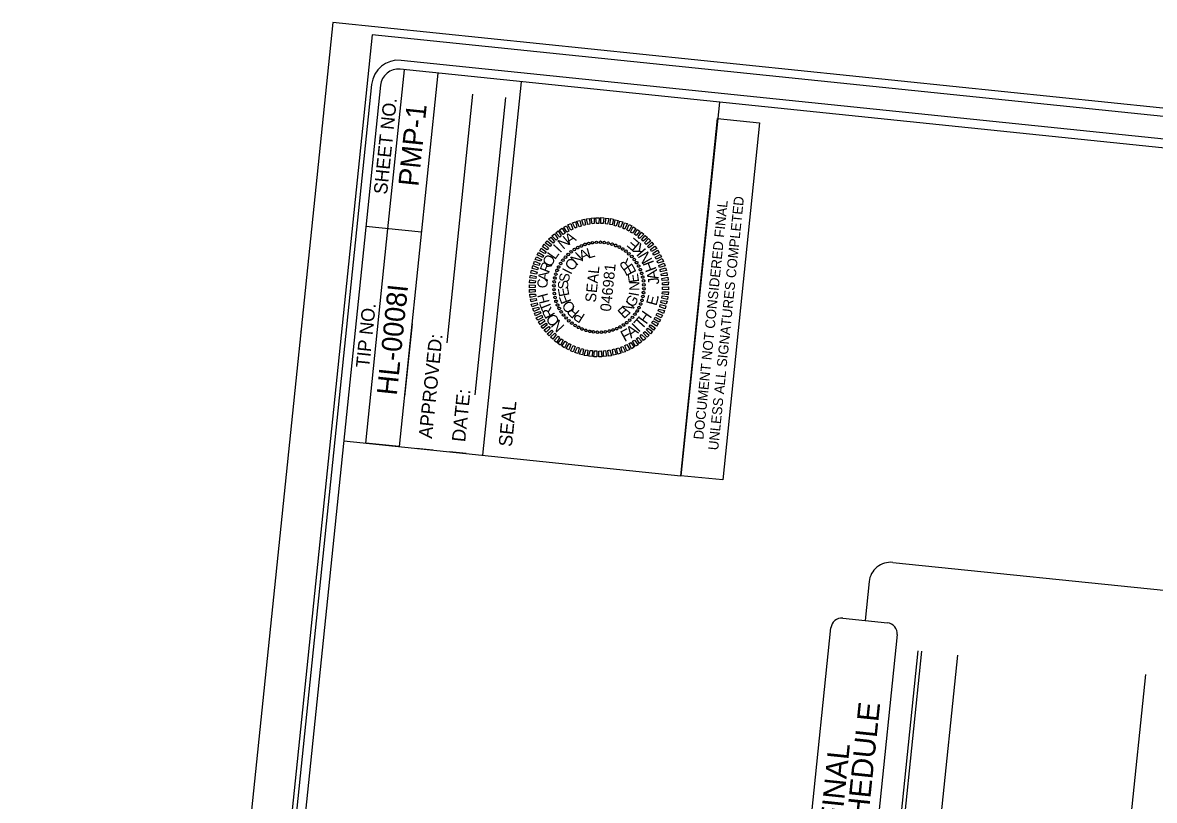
# Model space of a CAD drawing. Extents: x 2077770 to 2079037, y 247476 to 249877.
# Drawn here: x 2077770 to 2078401, y 249383 to 249816 of the extents above; entities that cross this region are included whole.
import ezdxf

# ---------------------------------------------------------------- set-up
doc = ezdxf.new("R2010")
doc.units = 0
for name, color, linetype in [('Default', 7, 'Continuous'), ('Sheet Data Field CELL', 7, 'Continuous'), ('Sheet Plot Border Inside CELL', 7, 'Continuous'), ('Sheet Plot Border Outside CELL', 7, 'Continuous'), ('Sheet Sticker Exception Certification CELL', 7, 'Continuous'), ('Sheet Title CELL', 7, 'Continuous')]:
    doc.layers.add(name, color=color, linetype=linetype)

msp = doc.modelspace()

# ---------------------------------------------------------------- linework, layer by layer
at = {"layer": 'Default'}
for p, q in [((2078081.68, 249691.84), (2078081.68, 249691.84)), ((2078083.72, 249692.63), (2078083.72, 249692.63)), ((2078085.79, 249693.22), (2078085.79, 249693.22)), ((2078087.94, 249693.61), (2078087.94, 249693.61)), ((2078090.17, 249693.78), (2078090.17, 249693.78)), ((2078092.34, 249693.85), (2078092.34, 249693.85)), ((2078094.53, 249693.68), (2078094.53, 249693.68)), ((2078096.71, 249693.3), (2078096.71, 249693.3)), ((2078098.81, 249692.73), (2078098.81, 249692.73)), ((2078100.85, 249692.07), (2078100.85, 249692.07)), ((2078072.83, 249685.51), (2078072.83, 249685.51)), ((2078074.35, 249687.12), (2078074.35, 249687.12)), ((2078076, 249688.5), (2078076, 249688.5)), ((2078077.8, 249689.83), (2078077.8, 249689.83)), ((2078079.67, 249690.89), (2078079.67, 249690.89)), ((2078102.87, 249691.16), (2078102.87, 249691.16)), ((2078104.77, 249690.06), (2078104.77, 249690.06)), ((2078106.6, 249688.86), (2078106.6, 249688.86)), ((2078108.27, 249687.44), (2078108.27, 249687.44)), ((2078109.87, 249685.91), (2078109.87, 249685.91)), ((2078069.11, 249680.12), (2078069.11, 249680.12)), ((2078070.21, 249682.01), (2078070.21, 249682.01)), ((2078071.4, 249683.85), (2078071.4, 249683.85)), ((2078111.26, 249684.26), (2078111.26, 249684.26)), ((2078112.58, 249682.47), (2078112.58, 249682.47)), ((2078113.64, 249680.6), (2078113.64, 249680.6)), ((2078066.96, 249673.96), (2078066.96, 249673.96)), ((2078067.53, 249676.06), (2078067.53, 249676.06)), ((2078068.2, 249678.1), (2078068.2, 249678.1)), ((2078114.59, 249678.59), (2078114.59, 249678.59)), ((2078115.39, 249676.55), (2078115.39, 249676.55)), ((2078115.98, 249674.48), (2078115.98, 249674.48)), ((2078066.41, 249669.59), (2078066.41, 249669.59)), ((2078066.49, 249667.42), (2078066.49, 249667.42)), ((2078066.59, 249671.78), (2078066.59, 249671.78)), ((2078091.51, 249668.76), (2078091.51, 249668.76)), ((2078116.36, 249672.33), (2078116.36, 249672.33)), ((2078116.53, 249670.1), (2078116.53, 249670.1)), ((2078116.61, 249667.93), (2078116.61, 249667.93)), ((2078066.66, 249665.19), (2078066.66, 249665.19)), ((2078067.04, 249663.04), (2078067.04, 249663.04)), ((2078067.63, 249660.97), (2078067.63, 249660.97)), ((2078115.49, 249661.46), (2078115.49, 249661.46)), ((2078116.06, 249663.56), (2078116.06, 249663.56)), ((2078116.43, 249665.73), (2078116.43, 249665.73)), ((2078068.43, 249658.93), (2078068.43, 249658.93)), ((2078069.38, 249656.92), (2078069.38, 249656.92)), ((2078070.44, 249655.05), (2078070.44, 249655.05)), ((2078112.81, 249655.5), (2078112.81, 249655.5)), ((2078113.91, 249657.4), (2078113.91, 249657.4)), ((2078114.82, 249659.41), (2078114.82, 249659.41)), ((2078071.76, 249653.25), (2078071.76, 249653.25)), ((2078073.15, 249651.6), (2078073.15, 249651.6)), ((2078074.75, 249650.08), (2078074.75, 249650.08)), ((2078076.42, 249648.65), (2078076.42, 249648.65)), ((2078078.25, 249647.46), (2078078.25, 249647.46)), ((2078105.22, 249647.69), (2078105.22, 249647.69)), ((2078107.01, 249649.01), (2078107.01, 249649.01)), ((2078108.67, 249650.4), (2078108.67, 249650.4)), ((2078110.19, 249652), (2078110.19, 249652)), ((2078111.62, 249653.66), (2078111.62, 249653.66)), ((2078080.15, 249646.36), (2078080.15, 249646.36)), ((2078082.17, 249645.44), (2078082.17, 249645.44)), ((2078084.21, 249644.78), (2078084.21, 249644.78)), ((2078086.31, 249644.21), (2078086.31, 249644.21)), ((2078088.48, 249643.84), (2078088.48, 249643.84)), ((2078090.68, 249643.66), (2078090.68, 249643.66)), ((2078092.85, 249643.74), (2078092.85, 249643.74)), ((2078095.08, 249643.91), (2078095.08, 249643.91)), ((2078097.23, 249644.29), (2078097.23, 249644.29)), ((2078099.3, 249644.88), (2078099.3, 249644.88)), ((2078101.34, 249645.68), (2078101.34, 249645.68)), ((2078103.35, 249646.62), (2078103.35, 249646.62)), ((2078237.64, 249157.39), (2078269.5, 249466.05)), ((2078239.63, 249157.18), (2078271.49, 249465.85)), ((2078259.7, 249155.11), (2078291.55, 249463.77)), ((2078364.43, 249144.31), (2078396.28, 249452.98))]:
    msp.add_line(p, q, dxfattribs=at)
for points in [[(2078075.9, 249700.63), (2078074.28, 249703.46), (2078075.87, 249704.25), (2078076.97, 249701.22)], [(2078078.22, 249701.7), (2078076.77, 249704.66), (2078078.38, 249705.15), (2078079.23, 249702.2)], [(2078080.46, 249702.47), (2078079.27, 249705.56), (2078080.93, 249706.04), (2078081.61, 249702.85)], [(2078082.89, 249703.12), (2078081.91, 249706.29), (2078083.51, 249706.68), (2078083.99, 249703.51)], [(2078085.36, 249703.67), (2078084.55, 249706.97), (2078086.22, 249707.1), (2078086.44, 249703.91)], [(2078087.81, 249704.02), (2078087.19, 249707.25), (2078088.91, 249707.38), (2078088.89, 249704.21)], [(2078090.24, 249704.22), (2078089.88, 249707.53), (2078091.59, 249707.5), (2078091.46, 249704.3)], [(2078092.66, 249704.28), (2078092.6, 249707.55), (2078094.3, 249707.48), (2078093.87, 249704.25)], [(2078095.15, 249704.07), (2078095.34, 249707.32), (2078097.03, 249707.14), (2078096.35, 249703.95)], [(2078097.64, 249703.76), (2078098.07, 249706.99), (2078099.7, 249706.72), (2078098.82, 249703.54)], [(2078100, 249703.27), (2078100.62, 249706.42), (2078102.29, 249706.05), (2078101.17, 249702.9)], [(2078102.49, 249702.61), (2078103.21, 249705.65), (2078104.86, 249705.13), (2078103.5, 249702.1)], [(2078104.81, 249701.72), (2078105.78, 249704.73), (2078107.38, 249704.22), (2078105.82, 249701.21)], [(2078067.74, 249695.09), (2078065.36, 249697.39), (2078066.68, 249698.46), (2078068.58, 249695.96)], [(2078069.66, 249696.7), (2078067.55, 249699.08), (2078068.86, 249700.15), (2078070.54, 249697.36)], [(2078071.63, 249698.25), (2078069.63, 249700.77), (2078071.08, 249701.68), (2078072.7, 249698.85)], [(2078073.73, 249699.55), (2078071.89, 249702.2), (2078073.43, 249702.99), (2078074.73, 249700.05)], [(2078107.12, 249700.72), (2078108.34, 249703.71), (2078109.81, 249702.91), (2078108.11, 249700.07)], [(2078109.21, 249699.5), (2078110.67, 249702.47), (2078112.14, 249701.56), (2078110.25, 249698.89)], [(2078111.39, 249698.27), (2078112.93, 249700.98), (2078114.4, 249700.07), (2078112.28, 249697.58)], [(2078113.41, 249696.86), (2078115.19, 249699.49), (2078116.48, 249698.35), (2078114.22, 249695.97)], [(2078062.75, 249689.67), (2078060.06, 249691.31), (2078061.06, 249692.71), (2078063.45, 249690.55)], [(2078064.3, 249691.47), (2078061.59, 249693.51), (2078062.77, 249694.7), (2078065.01, 249692.5)], [(2078066, 249693.36), (2078063.45, 249695.48), (2078064.68, 249696.66), (2078066.79, 249694.23)], [(2078115.25, 249695.16), (2078117.21, 249697.67), (2078118.56, 249696.58), (2078116.12, 249694.42)], [(2078116.98, 249693.47), (2078119.19, 249695.86), (2078120.37, 249694.63), (2078117.8, 249692.68)], [(2078118.69, 249691.54), (2078120.99, 249693.86), (2078122.01, 249692.5), (2078119.41, 249690.66)], [(2078120.26, 249689.72), (2078122.68, 249691.68), (2078123.75, 249690.36), (2078120.86, 249688.7)], [(2078059.07, 249683.21), (2078056.07, 249684.28), (2078056.72, 249685.77), (2078059.53, 249684.22)], [(2078060.2, 249685.36), (2078057.18, 249686.83), (2078057.92, 249688.16), (2078060.66, 249686.47)], [(2078061.37, 249687.5), (2078058.57, 249689.05), (2078059.42, 249690.52), (2078062.03, 249688.54)], [(2078121.6, 249687.57), (2078124.21, 249689.46), (2078125.11, 249688.01), (2078122.15, 249686.56)], [(2078122.9, 249685.52), (2078125.62, 249687.1), (2078126.43, 249685.71), (2078123.38, 249684.37)], [(2078057.37, 249678.41), (2078054.23, 249679.19), (2078054.65, 249680.81), (2078057.64, 249679.59)], [(2078058.18, 249680.89), (2078055, 249681.72), (2078055.57, 249683.37), (2078058.54, 249681.91)], [(2078123.91, 249683.21), (2078126.79, 249684.77), (2078127.43, 249683.15), (2078124.41, 249682.2)], [(2078124.89, 249680.95), (2078127.84, 249682.25), (2078128.37, 249680.64), (2078125.22, 249679.8)], [(2078125.71, 249678.65), (2078128.72, 249679.64), (2078129.17, 249678.09), (2078125.88, 249677.37)], [(2078056.02, 249671.21), (2078052.77, 249671.3), (2078052.98, 249672.93), (2078056.2, 249672.4)], [(2078056.32, 249673.6), (2078053.09, 249673.93), (2078053.31, 249675.57), (2078056.49, 249674.78)], [(2078056.73, 249676.07), (2078053.51, 249676.6), (2078053.98, 249678.21), (2078057.05, 249677.24)], [(2078126.25, 249676.13), (2078129.35, 249676.97), (2078129.64, 249675.38), (2078126.49, 249675.05)], [(2078126.65, 249673.68), (2078129.89, 249674.4), (2078130.06, 249672.67), (2078126.79, 249672.61)], [(2078056.02, 249668.7), (2078052.78, 249668.48), (2078052.75, 249670.19), (2078055.99, 249669.91)], [(2078056.07, 249666.28), (2078052.8, 249665.82), (2078052.82, 249667.47), (2078056.04, 249667.49)], [(2078126.95, 249671.23), (2078130.22, 249671.7), (2078130.2, 249670.04), (2078126.98, 249670.02)], [(2078127, 249668.81), (2078130.24, 249669.03), (2078130.27, 249667.32), (2078127.03, 249667.6)], [(2078056.37, 249663.84), (2078053.13, 249663.12), (2078052.95, 249664.85), (2078056.23, 249664.91)], [(2078056.77, 249661.39), (2078053.67, 249660.55), (2078053.38, 249662.14), (2078056.53, 249662.47)], [(2078057.31, 249658.87), (2078054.3, 249657.87), (2078053.85, 249659.42), (2078057.14, 249660.14)], [(2078126.29, 249661.45), (2078129.51, 249660.92), (2078129.04, 249659.3), (2078125.97, 249660.27)], [(2078126.7, 249663.92), (2078129.93, 249663.59), (2078129.71, 249661.95), (2078126.53, 249662.73)], [(2078126.99, 249666.3), (2078130.25, 249666.22), (2078130.03, 249664.58), (2078126.82, 249665.11)], [(2078058.13, 249656.57), (2078055.18, 249655.27), (2078054.65, 249656.88), (2078057.8, 249657.71)], [(2078059.1, 249654.31), (2078056.23, 249652.75), (2078055.59, 249654.37), (2078058.61, 249655.31)], [(2078123.95, 249654.3), (2078126.95, 249653.24), (2078126.3, 249651.75), (2078123.49, 249653.29)], [(2078124.84, 249656.62), (2078128.02, 249655.79), (2078127.45, 249654.14), (2078124.48, 249655.6)], [(2078125.65, 249659.1), (2078128.79, 249658.33), (2078128.37, 249656.71), (2078125.38, 249657.92)], [(2078060.12, 249651.99), (2078057.4, 249650.41), (2078056.58, 249651.8), (2078059.64, 249653.15)], [(2078061.42, 249649.95), (2078058.81, 249648.06), (2078057.91, 249649.51), (2078060.87, 249650.96)], [(2078062.76, 249647.8), (2078060.34, 249645.84), (2078059.27, 249647.15), (2078062.16, 249648.82)], [(2078120.26, 249647.84), (2078122.96, 249646.21), (2078121.96, 249644.8), (2078119.57, 249646.96)], [(2078121.64, 249650.01), (2078124.45, 249648.47), (2078123.6, 249647), (2078120.98, 249648.98)], [(2078122.82, 249652.16), (2078125.84, 249650.69), (2078125.1, 249649.36), (2078122.35, 249651.05)], [(2078064.33, 249645.98), (2078062.03, 249643.65), (2078061.01, 249645.01), (2078063.61, 249646.86)], [(2078066.04, 249644.04), (2078063.83, 249641.66), (2078062.65, 249642.88), (2078065.21, 249644.83)], [(2078067.77, 249642.35), (2078065.81, 249639.84), (2078064.46, 249640.94), (2078066.9, 249643.1)], [(2078069.61, 249640.66), (2078067.83, 249638.03), (2078066.54, 249639.16), (2078068.8, 249641.55)], [(2078115.28, 249642.43), (2078117.66, 249640.12), (2078116.34, 249639.05), (2078114.44, 249641.56)], [(2078117.02, 249644.16), (2078119.56, 249642.04), (2078118.34, 249640.86), (2078116.22, 249643.29)], [(2078118.72, 249646.04), (2078121.43, 249644.01), (2078120.25, 249642.82), (2078118.01, 249645.01)], [(2078071.62, 249639.24), (2078070.09, 249636.54), (2078068.62, 249637.44), (2078070.74, 249639.94)], [(2078073.81, 249638.01), (2078072.35, 249635.05), (2078070.88, 249635.95), (2078072.77, 249638.62)], [(2078075.9, 249636.79), (2078074.68, 249633.8), (2078073.21, 249634.61), (2078074.91, 249637.45)], [(2078078.21, 249635.8), (2078077.24, 249632.78), (2078075.64, 249633.3), (2078077.2, 249636.3)], [(2078080.53, 249634.91), (2078079.81, 249631.86), (2078078.15, 249632.39), (2078079.52, 249635.41)], [(2078102.56, 249635.05), (2078103.75, 249631.96), (2078102.09, 249631.47), (2078101.41, 249634.66)], [(2078104.8, 249635.82), (2078106.25, 249632.85), (2078104.64, 249632.37), (2078103.79, 249635.32)], [(2078107.12, 249636.89), (2078108.74, 249634.06), (2078107.15, 249633.26), (2078106.05, 249636.29)], [(2078109.29, 249637.97), (2078111.13, 249635.32), (2078109.59, 249634.52), (2078108.29, 249637.47)], [(2078111.39, 249639.26), (2078113.39, 249636.74), (2078111.94, 249635.84), (2078110.32, 249638.67)], [(2078113.36, 249640.82), (2078115.47, 249638.44), (2078114.16, 249637.37), (2078112.48, 249640.15)], [(2078083.02, 249634.25), (2078082.39, 249631.09), (2078080.72, 249631.47), (2078081.85, 249634.62)], [(2078085.38, 249633.75), (2078084.95, 249630.53), (2078083.32, 249630.8), (2078084.2, 249633.97)], [(2078087.86, 249633.45), (2078087.68, 249630.2), (2078085.99, 249630.37), (2078086.67, 249633.57)], [(2078090.36, 249633.24), (2078090.42, 249629.96), (2078088.72, 249630.04), (2078089.15, 249633.26)], [(2078092.77, 249633.29), (2078093.14, 249629.99), (2078091.43, 249630.01), (2078091.56, 249633.21)], [(2078095.21, 249633.49), (2078095.83, 249630.26), (2078094.11, 249630.14), (2078094.13, 249633.3)], [(2078097.66, 249633.84), (2078098.47, 249630.54), (2078096.8, 249630.41), (2078096.58, 249633.6)], [(2078100.13, 249634.39), (2078101.11, 249631.22), (2078099.51, 249630.84), (2078099.03, 249634)]]:
    msp.add_lwpolyline(points, close=True, dxfattribs=at)
for centre, major_axis in [((2078079.69, 249690.88), (-0.339, 0.635)), ((2078081.67, 249691.83), (-0.283, 0.662)), ((2078083.71, 249692.6), (-0.224, 0.684)), ((2078085.82, 249693.18), (-0.163, 0.701)), ((2078087.97, 249693.59), (-0.102, 0.713)), ((2078090.15, 249693.8), (-0.039, 0.719)), ((2078092.34, 249693.82), (0.024, 0.72)), ((2078094.52, 249693.66), (0.086, 0.715)), ((2078096.68, 249693.3), (0.148, 0.705)), ((2078098.8, 249692.76), (0.209, 0.689)), ((2078100.86, 249692.03), (0.268, 0.668)), ((2078102.85, 249691.13), (0.326, 0.642)), ((2078072.84, 249685.5), (-0.536, 0.481)), ((2078074.37, 249687.07), (-0.492, 0.526)), ((2078076.03, 249688.49), (-0.444, 0.567)), ((2078077.81, 249689.77), (-0.393, 0.603)), ((2078104.76, 249690.05), (0.38, 0.611)), ((2078106.57, 249688.82), (0.432, 0.576)), ((2078108.26, 249687.43), (0.481, 0.536)), ((2078109.82, 249685.9), (0.526, 0.492)), ((2078069.14, 249680.1), (-0.642, 0.326)), ((2078070.22, 249682.01), (-0.611, 0.38)), ((2078071.45, 249683.81), (-0.576, 0.432)), ((2078111.24, 249684.24), (0.567, 0.444)), ((2078112.52, 249682.46), (0.603, 0.393)), ((2078113.63, 249680.57), (0.635, 0.339)), ((2078114.58, 249678.6), (0.662, 0.283)), ((2078066.97, 249673.93), (-0.705, 0.148)), ((2078067.51, 249676.05), (-0.689, 0.209)), ((2078068.24, 249678.11), (-0.668, 0.268)), ((2078115.35, 249676.55), (0.684, 0.224)), ((2078115.94, 249674.45), (0.701, 0.163)), ((2078116.34, 249672.29), (0.713, 0.102)), ((2078066.44, 249669.59), (-0.72, 0.024)), ((2078066.47, 249667.4), (-0.719, -0.039)), ((2078066.61, 249671.77), (-0.715, 0.086)), ((2078116.41, 249665.75), (0.715, -0.086)), ((2078116.55, 249670.12), (0.719, 0.039)), ((2078116.58, 249667.93), (0.72, -0.024)), ((2078066.68, 249665.22), (-0.713, -0.102)), ((2078067.08, 249663.07), (-0.701, -0.163)), ((2078067.67, 249660.96), (-0.684, -0.224)), ((2078114.78, 249659.41), (0.668, -0.268)), ((2078115.51, 249661.47), (0.689, -0.209)), ((2078116.05, 249663.59), (0.705, -0.148)), ((2078068.44, 249658.91), (-0.662, -0.283)), ((2078069.39, 249656.94), (-0.635, -0.339)), ((2078070.5, 249655.06), (-0.603, -0.393)), ((2078071.78, 249653.28), (-0.567, -0.444)), ((2078111.57, 249653.7), (0.576, -0.432)), ((2078112.8, 249655.51), (0.611, -0.38)), ((2078113.88, 249657.41), (0.642, -0.326)), ((2078073.2, 249651.62), (-0.526, -0.492)), ((2078074.76, 249650.09), (-0.481, -0.536)), ((2078076.45, 249648.7), (-0.432, -0.576)), ((2078078.26, 249647.46), (-0.38, -0.611)), ((2078103.33, 249646.64), (0.339, -0.635)), ((2078105.21, 249647.75), (0.393, -0.603)), ((2078106.99, 249649.02), (0.444, -0.567)), ((2078108.65, 249650.45), (0.492, -0.526)), ((2078110.18, 249652.01), (0.536, -0.481)), ((2078080.17, 249646.39), (-0.326, -0.642)), ((2078082.16, 249645.49), (-0.268, -0.668)), ((2078084.22, 249644.76), (-0.209, -0.689)), ((2078086.34, 249644.22), (-0.148, -0.705)), ((2078088.5, 249643.86), (-0.086, -0.715)), ((2078090.68, 249643.69), (-0.024, -0.72)), ((2078092.87, 249643.71), (0.039, -0.719)), ((2078095.05, 249643.93), (0.102, -0.713)), ((2078097.2, 249644.33), (0.163, -0.701)), ((2078099.3, 249644.92), (0.224, -0.684)), ((2078101.35, 249645.69), (0.283, -0.662))]:
    msp.add_ellipse(centre, major_axis=major_axis, ratio=0.999708, dxfattribs=at)
at = {"layer": 'Sheet Plot Border Inside CELL'}
msp.add_lwpolyline([(2078843.53, 248043.45), (2079014.62, 249701.14), (2077965.1, 249809.47), (2077794, 248151.77)], close=True, dxfattribs=at)
at = {"layer": 'Sheet Plot Border Outside CELL'}
msp.add_lwpolyline([(2077943.23, 249816.25), (2077770.34, 248141.15), (2078864.51, 248028.21), (2079037.4, 249703.31)], close=True, dxfattribs=at)
at = {"layer": 'Sheet Sticker Exception Certification CELL'}
for p, q in [((2078137.25, 249563.74), (2078157.62, 249762.74)), ((2078157.63, 249762.74), (2078181.01, 249760.35)), ((2078181, 249760.35), (2078160.63, 249561.35)), ((2078160.63, 249561.35), (2078137.25, 249563.74))]:
    msp.add_line(p, q, dxfattribs=at)
at = {"layer": 'Sheet Title CELL'}
for p, q in [((2077973.96, 249701.36), (2077983.11, 249790.01)), ((2078001.76, 249788.09), (2077980.28, 249579.94)), ((2078026.91, 249575.13), (2078048.39, 249783.28)), ((2078006.87, 249637.74), (2078021.18, 249776.45)), ((2078022.59, 249608.75), (2078039.7, 249774.54)), ((2078158.73, 249771.89), (2078137.25, 249563.74)), ((2077961.63, 249581.87), (2077973.96, 249701.36)), ((2077992.62, 249699.44), (2077961.66, 249702.63)), ((2077987.35, 249648.32), (2077983.18, 249607.92)), ((2077949.33, 249583.14), (2078137.25, 249563.74)), ((2077980.28, 249579.94), (2077961.63, 249581.87)), ((2077998.94, 249578.02), (2077989.61, 249578.98)), ((2078017.58, 249576.09), (2078008.26, 249577.06)), ((2078255.28, 249515.4), (2078621.17, 249477.81)), ((2078242.12, 249504.69), (2078239.88, 249483.01)), ((2078227.41, 249484.3), (2078252.36, 249481.72)), ((2078188.97, 249170.27), (2078220.83, 249478.94)), ((2078257.71, 249475.14), (2078225.85, 249166.47))]:
    msp.add_line(p, q, dxfattribs=at)
for points in [[(2078995.88, 249690.51), (2077981.27, 249795.23)], [(2078995.37, 249685.54), (2077980.76, 249790.26)], [(2077964.81, 249781.85), (2077813.88, 248319.62)], [(2077969.78, 249781.34), (2077824, 248368.84)]]:
    msp.add_lwpolyline(points, dxfattribs=at)
for centre, radius, start, end in [((2077979.73, 249780.31), 15, 84.10721, 174.10672), ((2077979.73, 249780.31), 10, 84.10721, 174.10721), ((2078254.05, 249503.46), 12, 84.10721, 174.10721), ((2078226.79, 249478.32), 6, 84.10721, 174.10721), ((2078251.74, 249475.75), 6, 354.10721, 84.10721)]:
    msp.add_arc(centre, radius, start, end, dxfattribs=at)

# ---------------------------------------------------------------- texts
at = {"layer": 'Default'}
for s, height, rotation, p in [('A', 5.95, 32.72436, (2078074.88, 249692.19)), ('I', 5.98, 47.12735, (2078069.88, 249687.58)), ('N', 5.99, 39.92612, (2078071.64, 249689.56)), ('E', 6.29, 139.60023, (2078114.92, 249693.08)), ('K', 6.36, 131.31631, (2078118.18, 249689.46)), ('O', 5.85, 61.52837, (2078064.78, 249679.61)), ('L', 5.93, 54.32808, (2078067.07, 249683.8)), ('N', 5.99, 44.58382, (2078079.15, 249680.54)), ('A', 5.89, 25.86747, (2078082.03, 249683.11)), ('L', 5.79, 16.50806, (2078085.66, 249684.69)), ('R', 5.99, 126.58862, (2078110.61, 249680.96)), ('N', 6.36, 120.59048, (2078121.57, 249684.13)), ('R', 5.75, 68.72831, (2078063.69, 249676.35)), ('I', 5.83, 63.29681, (2078075.92, 249675.49)), ('O', 5.94, 53.94069, (2078076.82, 249677.41)), ('SEAL', 5.998, 84.10721, (2078089.76, 249660.09)), ('046981', 5.998, 84.10721, (2078098.14, 249655.03)), ('E', 5.96, 117.2313, (2078112.59, 249677.19)), ('H', 6.27, 110.60649, (2078123.78, 249678.69)), ('A', 6.15, 101.76619, (2078124.92, 249673.61)), ('C', 5.66, 90.32708, (2078062.96, 249668.24)), ('A', 5.64, 83.12753, (2078063.06, 249672.2)), ('S', 5.64, 82.00761, (2078074.78, 249671.29)), ('E', 5.74, 98.51897, (2078113.98, 249671.72)), ('J', 6.08, 96.50837, (2078125.23, 249670.53)), ('E', 5.77, 100.71827, (2078075.15, 249664.16)), ('S', 5.67, 91.36282, (2078074.46, 249667.7)), ('N', 5.65, 89.1636, (2078114.07, 249666.73)), ('H', 5.82, 104.72669, (2078064.16, 249660.47)), ('F', 5.89, 110.07424, (2078076.31, 249660.83)), ('O', 5.98, 128.78845, (2078078.91, 249657.24)), ('N', 5.95, 51.74116, (2078108.39, 249653.54)), ('G', 5.86, 61.09745, (2078111.01, 249657.09)), ('I', 5.65, 79.80841, (2078113.58, 249663.41)), ('E', 6.04, 75.1649, (2078123.56, 249658.13)), ('.', 6, 82.27423, (2078124.63, 249662.18)), ('T', 5.91, 111.92698, (2078065.47, 249657.07)), ('R', 5.97, 119.12771, (2078067.31, 249653.46)), ('R', 5.93, 138.14686, (2078081.17, 249655.25)), ('P', 5.84, 147.5061, (2078084.19, 249653.33)), ('E', 5.99, 42.3841, (2078105.39, 249650.84)), ('H', 6.3, 54.98056, (2078117.92, 249647.73)), ('O', 5.99, 126.32895, (2078070.04, 249649.71)), ('N', 5.96, 133.53071, (2078072.69, 249647.13)), ('I', 6.37, 44.37837, (2078113.6, 249643.23)), ('T', 6.36, 48.18032, (2078115.25, 249644.75)), ('F', 6.29, 28.52145, (2078105.79, 249638.16)), ('A', 6.35, 35.53806, (2078109.42, 249640.14)), ('PAVEMENT MARKING SCHEDULE', 12, 84.10721, (2078221.66, 249178.8)), ('PROJECT HL-0008I FINAL', 12, 84.10721, (2078211.41, 249219.69))]:
    msp.add_text(s, height=height, rotation=rotation, dxfattribs=at).set_placement(p)
at = {"layer": 'Sheet Data Field CELL'}
for s, height, p in [('SHEET NO.', 7.5, (2077973.42, 249720.24)), ('PMP-1', 11.25, (2077990.88, 249724.61)), ('HL-0008I', 11.25, (2077978.86, 249608.17)), ('TIP NO.', 7.5, (2077963.49, 249623.59)), ('APPROVED:', 7.5, (2077998.44, 249584.18)), ('DATE:', 7.5, (2078016.96, 249582.27)), ('SEAL', 7.5, (2078042.99, 249579.58))]:
    msp.add_text(s, height=height, rotation=84.10721, dxfattribs=at).set_placement(p)
at = {"layer": 'Sheet Sticker Exception Certification CELL'}
for s, p in [('DOCUMENT NOT CONSIDERED FINAL', (2078149.69, 249583.65)), ('UNLESS ALL SIGNATURES COMPLETED', (2078157.93, 249577.71))]:
    msp.add_text(s, height=5.5, rotation=84.15492, dxfattribs=at).set_placement(p)

doc.saveas('drawing.dxf')
